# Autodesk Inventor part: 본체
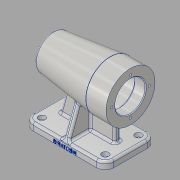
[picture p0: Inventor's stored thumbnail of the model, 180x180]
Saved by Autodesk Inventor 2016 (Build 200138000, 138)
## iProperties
Created: 2018-09
Part Number: 본체
Material: 알루미늄 6061
Document SubType Name: Modeling
Designer: Administrator
Density: 2.7 g/cm^3
Appearance: 알루미늄 - 평지
Mass: 732.752 g
Surface Area: 663.622 cm^2
Volume: 271.389 cm^3
Author: Administrator
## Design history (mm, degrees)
sketch "스케치1"
  geometry: L1 (-56, 35)-(56, 35); L2 (56, 35)-(56, -35); L3 (56, -35)-(-56, -35); L4 (-56, -35)-(-56, 35); L5 (-56, 35)-(56, -35); L6 (56, 35)-(-56, -35); 1 further point
  constraints: 12 end point, 2 midpoint, 2 parallel, 1 horizontal, 1 perpendicular
  dimensions: "d0" = 112 distance of L1.start L1.end; "d1" = 70 distance of L1.end L2.end
extrude "돌출1" new body sketch "스케치1" distance "d2" = 10; taper "d3" = 0 deg
sketch "스케치2"
  geometry: L1 (56, 74)-(-56, 74); L2 (-56, 0)-(56, 0) reference; L3 (-56, 74)-(-56, 108); L4 (-56, 108)-(-28, 108); L5 (-28, 108)-(52.27, 98.144); A1 r 80 centre (-24, 74) between (56, 74) and (52.27, 98.144); 2 further points
  constraints: 8 end point, 2 point on circle, 1 centre point, 1 perpendicular, 1 point on line, 1 vertical, 1 vertical alignment
  dimensions: "d4" = 74 distance between parallel lines of L2 L1; "d5" = 80 radius of A1; "d6" = 68 diameter of L4 L1; "d7" = 28 distance of L3.end L4.end; "d8" = 7 deg angle of L5 L4; "d9" = 112 distance of L1.start L1.end
revolve "회전1" sketch "스케치2" stored, may be unused: angle "d10" = 90 deg
sketch "스케치4"
  geometry: L1 (-4, 4)-(4, 4); L2 (4, 4)-(4, -4); L3 (4, -4)-(-4, -4); L4 (-4, -4)-(-4, 4); L5 (-4, 4)-(4, -4); L6 (4, 4)-(-4, -4); 1 further point
  constraints: 12 end point, 2 midpoint, 2 parallel, 1 horizontal, 1 perpendicular
  dimensions: "d15" = 8 distance of L2.end L3.end; "d16" = 8 distance of L1.end L2.end
extrude "돌출2" join sketch "스케치4" stored distance "d17" = 10; taper "d18" = 0 deg
sketch "스케치5"
  geometry: L1 (56, 10)-(-56, 10) reference; L2 (38, 10)-(29.495, 41.742); L3 (56, 0)-(56, 10) reference; 1 further point
  constraints: 2 end point, 1 point on line
  dimensions: "d19" = 105 deg angle of L2 L1; "d20" = 18 distance from line of L2.start L3
feature "리브1" sketch "스케치5" dims "d21" = 1, "d22" = 8, "d23" = 0, "d24" = 0, "d25" = 1, "d26" = 1
sketch "스케치6"
  geometry: L1 (-56, 10)-(56, 10) reference; L2 (-38, 10)-(-38, 31.299); L3 (-56, 0)-(-56, 10) reference; 1 further point
  constraints: 2 end point, 1 point on line, 1 vertical
  dimensions: "d27" = 18 distance between parallel lines of L2 L3
feature "리브2" sketch "스케치6" dims "d28" = 1, "d29" = 8, "d30" = 0, "d31" = 0, "d32" = 1, "d33" = 1
fillet "모깎기1" dims "d34" = 12
fillet "모깎기2" dims "d35" = 3
sketch "스케치8"
  geometry: L1 (-34.819, 8.026)-(-27.191, 28.984); L2 (-35, 0)-(-35, 7) reference; A1 r 3 centre (-32, 7) between (-32, 10) and (-35, 7) reference; 1 further point
  constraints: 2 end point, 1 point on circle, 1 tangent
  dimensions: "d36" = 20 deg angle of L1 L2
feature "리브3" sketch "스케치8" dims "d37" = 1, "d38" = 8, "d39" = 0, "d40" = 0, "d41" = 1, "d42" = 1
sketch "스케치9"
  geometry: L1 (-56, 40)-(-56, 108) reference; L2 (-56, 74)-(50, 74); L3 (-56, 95)-(-41, 95); L4 (-41, 95)-(-41, 98); L5 (-41, 98)-(13, 98); L6 (13, 98)-(13, 95); L7 (13, 95)-(25, 95); L8 (25, 95)-(25, 91.5); L9 (25, 91.5)-(43, 91.5); L10 (43, 91.5)-(43, 90); L11 (43, 90)-(47, 90); L12 (47, 90)-(47, 84.5); L13 (47, 84.5)-(50, 84.5); L14 (50, 84.5)-(50, 74); L15 (-56, 95)-(-56, 74); 1 further point
  constraints: 28 end point, 6 perpendicular, 4 horizontal, 2 point on line, 2 vertical, 1 collinear, 1 midpoint
  dimensions: "d43" = 42 diameter of L3 L2; "d44" = 48 diameter of L5 L2; "d46" = 35 diameter of L9 L2; "d47" = 32 diameter of L11 L2; "d48" = 21 diameter of L13 L2; "d49" = 3 distance between parallel lines of L12 L14; "d50" = 4 distance between parallel lines of L10 L12; "d51" = 18 distance between parallel lines of L8 L10; "d52" = 12 distance between parallel lines of L6 L8; "d53" = 54 distance between parallel lines of L4 L6; "d54" = 15 distance between parallel lines of L1 L4
revolve "회전2" sketch "스케치9" stored, may be unused: angle "d55" = 90 deg
fillet "모깎기3" dims "d56" = 0.3, "d57" = 3
chamfer "모따기1" distance "d58" = 1; stored, may be unused: second distance "d59" = 2, angle "d60" = 45 deg
sketch "스케치10"
  geometry: L1 (0, 0)-(-26, 0); C1 r 34 at (0, 0) reference; 2 further points
  constraints: 2 end point, 1 coincident, 1 horizontal
  dimensions: "d61" = 26 distance of L1.start L1.end
hole "구멍1" sketch "스케치10" at (-26, 0) diameter "d62" = 3.242; stored, may be unused: countersink angle "d66" = 90 deg, drill point angle "d68" = 118 deg; dims "d63" = 8, "d64" = 4, "d65" = 2, "d67" = 11
sketch "스케치11"
  geometry: L1 (88, 0)-(0, 0) reference; L2 (100, 0)-(100, 7) reference; 2 further points
  constraints: 1 other
  dimensions: "d72" = 3 distance from line of point (44, 3) L1; "d73" = 56 distance from line of point (44, 3) L2
feature "엠보싱1" sketch "스케치11" dims "d0" = 112, "d1" = 70, "d74" = 0.5, "d75" = 0
sketch "스케치12"
  geometry: L1 (-44, 35)-(44, 35) reference; L2 (56, 23)-(56, -23) reference; L3 (44, -35)-(-44, -35) reference; L4 (-56, -23)-(-56, 23) reference; A1 r 12 centre (44, 23) between (56, 23) and (44, 35) reference; A2 r 12 centre (44, -23) between (44, -35) and (56, -23) reference; A3 r 12 centre (-44, -23) between (-56, -23) and (-44, -35) reference; A4 r 12 centre (-44, 23) between (-44, 35) and (-56, 23) reference; 5 further points
  constraints: 4 coincident
hole "구멍2" sketch "스케치12" at (-44, 23), (-44, -23), (44, -23), (44, 23) diameter "d76" = 5.5; stored, may be unused: countersink angle "d80" = 90 deg, drill point angle "d82" = 118 deg; dims "d77" = 8, "d78" = 9.5, "d79" = 5.4, "d81" = 11
fillet "모깎기7" dims "d86" = 3
fillet "모깎기8" dims "d87" = 3
fillet "모깎기9" dims "d88" = 3
sketch "스케치13"
  geometry: L1 (0, 112.128)-(-58.878, 112.128); L2 (-58.878, 112.128)-(-58.878, -18.832); L3 (-58.878, -18.832)-(0, -18.832); L4 (0, -18.832)-(0, 112.128); 1 further point
  constraints: 8 end point, 2 parallel, 1 horizontal, 1 perpendicular, 1 vertical alignment
extrude "돌출3" cut sketch "스케치13" stored distance "d89" = 0; taper "d90" = 0 deg
node "솔리드1"
mirror "대칭1"
pattern_circular "원형 패턴1" dims angle "d70" = 360 deg
node "투영된 루프2"
